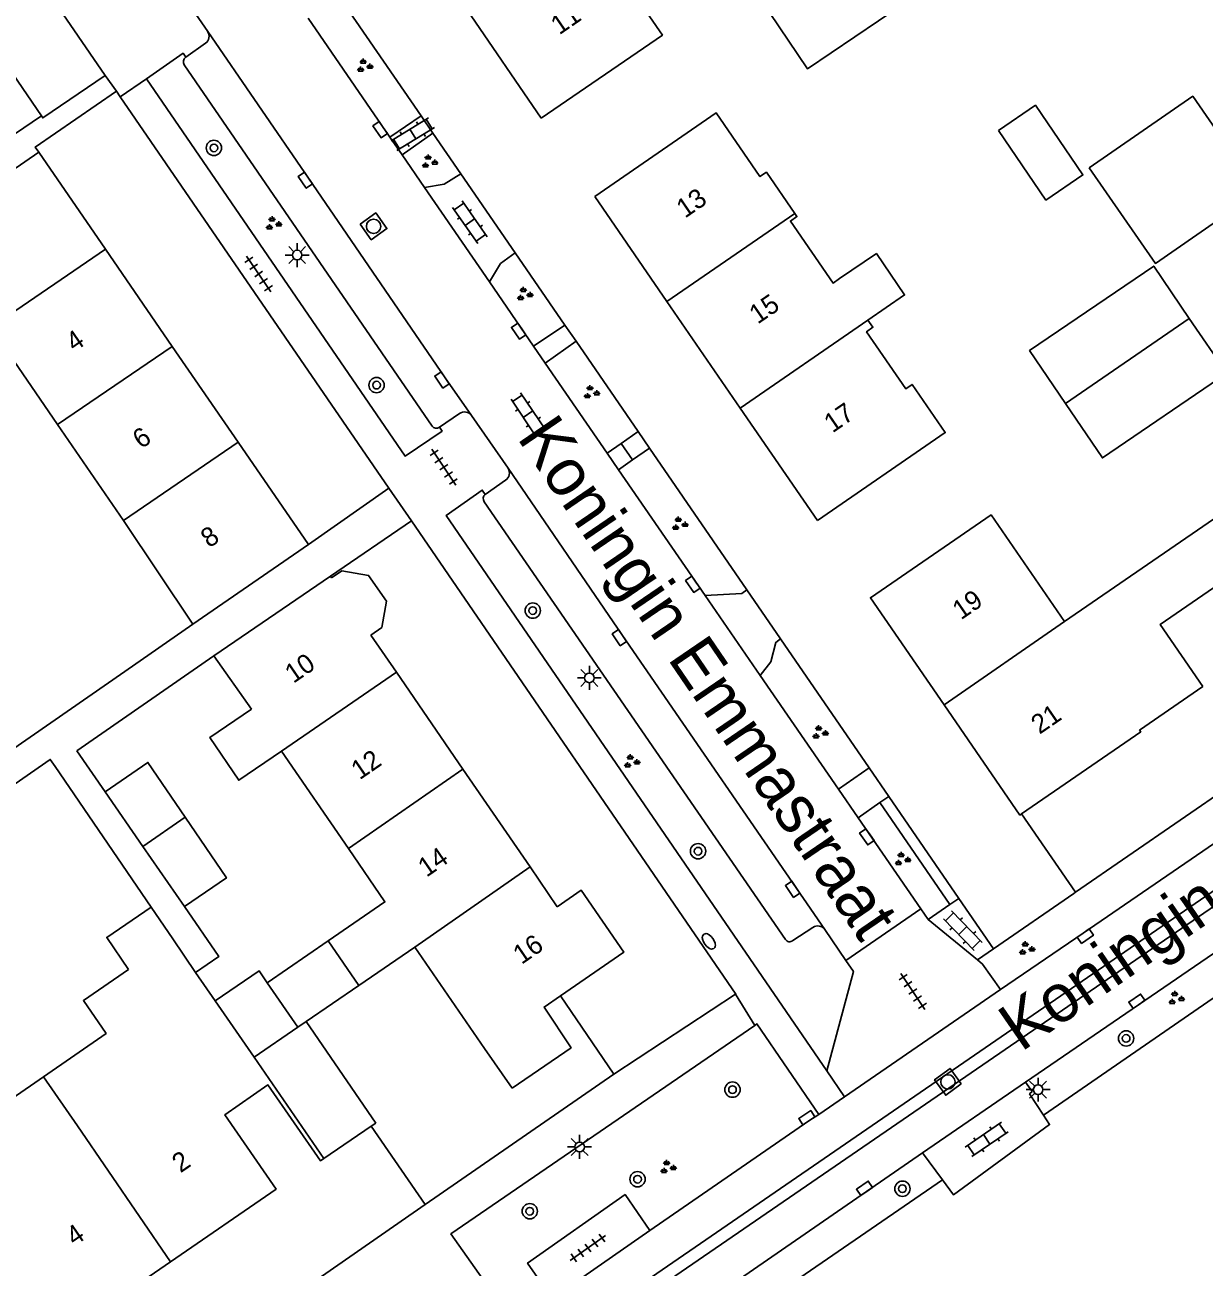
# Model space of a CAD drawing. Extents: x 137999 to 141000, y 397500 to 400501.
# Drawn here: x 138164.6 to 138226.2, y 399868.5 to 399933.3 of the extents above; entities that cross this region are included whole.
import ezdxf

# ---------------------------------------------------------------- set-up
doc = ezdxf.new("R2010")
doc.units = 0
for name, color, linetype in [('gg-afsc-erfafscheiding', 7, 'Continuous'), ('gg-afsc-hekwerk', 7, 'Continuous'), ('gg-afsc-muur', 7, 'Continuous'), ('gg-anno-huisnummerreeks BGT', 7, 'Continuous'), ('gg-anno-openbare ruimte label', 7, 'Continuous'), ('gg-bbg-bijgebouw', 7, 'Continuous'), ('gg-bbg-gedigitaliseerde bebouwing', 7, 'Continuous'), ('gg-bbg-gedigitaliseerde bijgebouw', 7, 'Continuous'), ('gg-bbg-hoofdgebouw', 7, 'Continuous'), ('gg-bbg-luifel en loopbrug', 7, 'Continuous'), ('gg-bbg-tussenscheiding', 7, 'Continuous'), ('gg-knt-verharding', 7, 'Continuous'), ('gg-knt-verharding nz', 7, 'Continuous'), ('gt-grn-groengrens', 7, 'Continuous'), ('gt-grn-vlakafsluiter', 7, 'Continuous'), ('gt-grn-weggrens', 7, 'Continuous'), ('gt-symb-boom', 7, 'Continuous'), ('gt-symb-brandkraan', 7, 'Continuous'), ('gt-symb-groenvak', 7, 'Continuous'), ('gt-symb-klinker verharding', 7, 'Continuous'), ('gt-symb-kolk', 7, 'Continuous'), ('gt-symb-lichtmast', 7, 'Continuous'), ('gt-symb-rioolschacht', 7, 'Continuous'), ('gt-symb-tegel verharding', 7, 'Continuous')]:
    doc.layers.add(name, color=color, linetype=linetype)

# ---------------------------------------------------------------- blocks, each defined once
blk = doc.blocks.new('gt0-GRVAK')
at = {"layer": 'gt-symb-groenvak'}
for p, q in [((-0.11, 0.189), (-0.228, 0.24)), ((-0.182, 0.153), (0.088, 0.153)), ((-0.091, 0.211), (-0.156, 0.322)), ((-0.047, 0.214), (-0.047, 0.393)), ((-0.004, 0.211), (0.061, 0.322)), ((0.015, 0.189), (0.133, 0.24)), ((0.262, -0.052), (0.197, 0.059)), ((0.305, -0.049), (0.305, 0.13)), ((0.349, -0.052), (0.414, 0.059)), ((-0.245, -0.228), (-0.363, -0.177)), ((-0.318, -0.264), (-0.047, -0.264)), ((-0.226, -0.206), (-0.291, -0.095)), ((-0.183, -0.203), (-0.183, -0.024)), ((-0.139, -0.206), (-0.074, -0.095)), ((-0.12, -0.228), (-0.002, -0.177)), ((0.243, -0.074), (0.125, -0.023)), ((0.17, -0.11), (0.441, -0.11)), ((0.368, -0.074), (0.486, -0.023))]:
    blk.add_line(p, q, dxfattribs=at)
blk = doc.blocks.new('gt0-KL1')
at = {"layer": 'gt-symb-klinker verharding'}
for p, q in [((-1.15, 0.3), (1.15, 0.3)), ((-1, -0.3), (-1, 0.3)), ((-0.5, 0.3), (-0.5, 0.45)), ((0, -0.3), (0, 0.3)), ((0.5, 0.3), (0.5, 0.45)), ((1, -0.3), (1, 0.3)), ((-1.15, -0.3), (1.15, -0.3)), ((-0.5, -0.45), (-0.5, -0.3)), ((0.5, -0.45), (0.5, -0.3))]:
    blk.add_line(p, q, dxfattribs=at)
blk = doc.blocks.new('gt0-KOLK')
at = {"layer": 'gt-symb-kolk'}
blk.add_lwpolyline([(0, 0), (0.375, 0), (0.375, 0.4), (-0.375, 0.4), (-0.375, 0), (0, 0)], dxfattribs=at)
blk = doc.blocks.new('gt0-BOOM')
at = {"layer": 'gt-symb-boom'}
for radius in [0.4, 0.2]:
    blk.add_circle((0, 0), radius, dxfattribs=at)
blk = doc.blocks.new('gt0-LMAST')
at = {"layer": 'gt-symb-lichtmast'}
for p, q in [((-0.182, 0.173), (-0.447, 0.438)), ((-0.005, 0.246), (-0.005, 0.621)), ((0.172, 0.173), (0.437, 0.438)), ((-0.255, -0.004), (-0.63, -0.004)), ((-0.182, -0.181), (-0.447, -0.446)), ((-0.005, -0.254), (-0.005, -0.629)), ((0.437, -0.446), (0.172, -0.181)), ((0.245, -0.004), (0.62, -0.004))]:
    blk.add_line(p, q, dxfattribs=at)
blk.add_circle((-0.005, -0.004), 0.25, dxfattribs=at)
blk = doc.blocks.new('gt0-TEG1')
at = {"layer": 'gt-symb-tegel verharding'}
for p, q in [((-1.125, 0), (1.125, 0)), ((-0.9, -0.25), (-0.9, 0.25)), ((-0.45, -0.25), (-0.45, 0.25)), ((0, -0.25), (0, 0.25)), ((0.45, -0.25), (0.45, 0.25)), ((0.9, -0.25), (0.9, 0.25))]:
    blk.add_line(p, q, dxfattribs=at)
blk = doc.blocks.new('gt0-RS')
at = {"layer": 'gt-symb-rioolschacht'}
blk.add_lwpolyline([(-0.5, -0.5), (0.5, -0.5), (0.5, 0.5), (-0.5, 0.5)], close=True, dxfattribs=at)
blk.add_circle((0, 0), 0.375, dxfattribs=at)
blk = doc.blocks.new('gt0-BR')
at = {"layer": 'gt-symb-brandkraan'}
for centre, radius, start, end in [((-0.244, 0), 0.206, 107.56694, 252.43307), ((0.599, -2.664), 3, 106.89205, 107.56694), ((0, -0.691), 0.938, 73.10799, 106.89205), ((-0.599, -2.664), 3, 72.43309, 73.10799), ((0.244, 0), 0.206, 287.56695, 72.43309), ((0.599, 2.664), 3, 252.43307, 253.10797), ((0, 0.691), 0.938, 253.10797, 286.89206), ((-0.599, 2.664), 3, 286.89206, 287.56695)]:
    blk.add_arc(centre, radius, start, end, dxfattribs=at)

msp = doc.modelspace()

# ---------------------------------------------------------------- linework, layer by layer
at = {"layer": 'gg-afsc-erfafscheiding'}
for p, q in [((138173.372, 399902.013), (138169.814, 399899.547)), ((138167.311, 399895.395), (138168.781, 399893.269)), ((138166.183, 399894.589), (138171.193, 399887.241)), ((138216.635, 399892.109), (138219.456, 399888.019))]:
    msp.add_line(p, q, dxfattribs=at)
for points in [[(138157.271, 399893.932), (138154.118, 399888.663), (138169.814, 399899.547)], [(138172.928, 399887.272), (138174.727, 399884.669), (138173.512, 399883.829)], [(138186.75, 399836.588), (138178.901, 399848.232), (138179.379, 399850.047), (138205.064, 399867.897), (138212.505, 399873.019)]]:
    msp.add_lwpolyline(points, dxfattribs=at)
at = {"layer": 'gg-afsc-hekwerk'}
for p, q in [((138219.456, 399888.019), (138234.264, 399898.232)), ((138219.362, 399887.954), (138219.456, 399888.019))]:
    msp.add_line(p, q, dxfattribs=at)
at = {"layer": 'gg-afsc-muur'}
for p, q in [((138167.311, 399895.395), (138174.472, 399900.357)), ((138195.357, 399878.535), (138192.572, 399882.619)), ((138185.501, 399871.719), (138195.357, 399878.535)), ((138182.684, 399875.809), (138185.501, 399871.719))]:
    msp.add_line(p, q, dxfattribs=at)
msp.add_lwpolyline([(138162.241, 399892.403), (138165.926, 399894.959), (138166.183, 399894.589)], dxfattribs=at)
at = {"layer": 'gg-bbg-bijgebouw'}
for p, q in [((138163.21, 399931.84), (138165.46, 399928.54)), ((138182.684, 399875.809), (138180.215, 399874.12)), ((138182.92, 399875.97), (138182.684, 399875.809))]:
    msp.add_line(p, q, dxfattribs=at)
at = {"layer": 'gg-bbg-gedigitaliseerde bebouwing'}
for p, q in [((138165.32, 399926.65), (138159.36, 399922.531)), ((138162.821, 399917.5), (138166.305, 399912.434)), ((138166.305, 399912.434), (138169.752, 399907.422)), ((138218.889, 399902.156), (138227.552, 399908.096)), ((138169.752, 399907.422), (138173.372, 399902.013)), ((138174.472, 399900.357), (138176.437, 399897.586)), ((138177.999, 399895.384), (138181.489, 399890.303)), ((138172.316, 399885.595), (138171.193, 399887.241)), ((138172.316, 399885.595), (138173.512, 399883.829)), ((138180.435, 399885.486), (138182.039, 399883.15)), ((138182.039, 399883.15), (138184.952, 399885.15)), ((138184.952, 399885.15), (138188.6, 399879.87)), ((138173.512, 399883.829), (138174.537, 399882.356)), ((138190.04, 399877.796), (138188.6, 399879.87))]:
    msp.add_line(p, q, dxfattribs=at)
for points in [[(138191.56, 399928.42), (138197.884, 399932.764), (138195.601, 399936.09), (138195.924, 399936.312)], [(138204.793, 399923.454), (138203.315, 399925.603), (138202.98, 399925.373), (138200.695, 399928.698), (138194.35, 399924.34)], [(138207.132, 399920.048), (138206.799, 399919.819), (138204.573, 399923.056), (138204.908, 399923.286), (138204.793, 399923.454)], [(138208.621, 399917.883), (138210.531, 399919.198), (138209.057, 399921.36), (138207.132, 399920.048)], [(138205.98, 399907.42), (138212.651, 399912.018), (138210.924, 399914.53), (138210.592, 399914.301), (138208.544, 399917.281), (138208.877, 399917.51), (138208.621, 399917.883)], [(138226.099, 399898.757), (138223.87, 399901.997), (138229.22, 399905.676)], [(138176.437, 399897.586), (138174.248, 399896.097), (138175.767, 399893.865), (138177.999, 399895.384)], [(138181.489, 399890.303), (138183.399, 399887.522), (138180.435, 399885.486)], [(138171.193, 399887.241), (138168.874, 399885.663), (138170.007, 399883.998)], [(138170.007, 399883.998), (138167.652, 399882.37), (138168.837, 399880.657), (138165.567, 399878.396)], [(138157.77, 399873.004), (138154.542, 399877.672), (138157.327, 399879.598), (138159.798, 399877.298), (138161.14, 399878.241), (138162.5, 399876.275), (138165.567, 399878.396)]]:
    msp.add_lwpolyline(points, dxfattribs=at)
at = {"layer": 'gg-bbg-gedigitaliseerde bijgebouw'}
for p, q in [((138159.316, 399924.381), (138165.46, 399928.54)), ((138170.759, 399890.409), (138168.781, 399893.269)), ((138172.928, 399887.272), (138170.759, 399890.409)), ((138178.846, 399880.973), (138177.252, 399883.299)), ((138179.285, 399881.274), (138178.846, 399880.973)), ((138182.92, 399875.97), (138179.285, 399881.274))]:
    msp.add_line(p, q, dxfattribs=at)
for points in [[(138211.634, 399935.184), (138205.466, 399930.997), (138203.471, 399933.935)], [(138220.174, 399925.837), (138223.626, 399920.844), (138229.027, 399924.578), (138225.574, 399929.571), (138220.174, 399925.837)], [(138215.439, 399927.783), (138217.364, 399929.096), (138219.84, 399925.464), (138217.915, 399924.152), (138215.439, 399927.783)], [(138225.387, 399917.966), (138223.538, 399920.702), (138217.056, 399916.29), (138218.934, 399913.53)], [(138218.934, 399913.53), (138220.863, 399910.696), (138227.35, 399915.112), (138225.387, 399917.966)], [(138172.97, 399891.934), (138171.023, 399894.795), (138168.781, 399893.269)], [(138172.97, 399891.934), (138175.125, 399888.767), (138172.928, 399887.272)], [(138177.252, 399883.299), (138176.824, 399883.923), (138174.537, 399882.356)]]:
    msp.add_lwpolyline(points, dxfattribs=at)
at = {"layer": 'gg-bbg-hoofdgebouw'}
for p, q in [((138191.56, 399928.42), (138187.668, 399934.091)), ((138165.32, 399926.65), (138168.802, 399921.588)), ((138198.124, 399918.85), (138194.35, 399924.34)), ((138168.802, 399921.588), (138172.291, 399916.515)), ((138201.947, 399913.288), (138198.124, 399918.85)), ((138172.291, 399916.515), (138175.733, 399911.511)), ((138205.98, 399907.42), (138201.947, 399913.288)), ((138175.733, 399911.511), (138179.4, 399906.18)), ((138179.4, 399906.18), (138173.372, 399902.013)), ((138174.472, 399900.357), (138180.55, 399904.52)), ((138180.55, 399904.52), (138180.611, 399904.431)), ((138182.659, 399901.449), (138183.994, 399899.506)), ((138183.994, 399899.506), (138187.468, 399894.448)), ((138226.099, 399898.757), (138222.803, 399896.482)), ((138187.468, 399894.448), (138190.975, 399889.341)), ((138190.975, 399889.341), (138192.398, 399887.269))]:
    msp.add_line(p, q, dxfattribs=at)
for points in [[(138218.889, 399902.156), (138215.05, 399907.72), (138208.75, 399903.39), (138212.59, 399897.808)], [(138180.611, 399904.431), (138181.139, 399904.793), (138182.545, 399904.56), (138183.487, 399903.218), (138183.232, 399901.843), (138182.659, 399901.449)], [(138216.635, 399892.109), (138216.55, 399892.05), (138212.59, 399897.808)], [(138222.803, 399896.482), (138222.86, 399896.4), (138216.635, 399892.109)], [(138192.572, 399882.619), (138195.871, 399884.888), (138193.648, 399888.127), (138192.398, 399887.269)], [(138192.572, 399882.619), (138191.712, 399882.027), (138193.121, 399879.905), (138190.04, 399877.796)], [(138180.215, 399874.12), (138180.04, 399874), (138177.29, 399877.97), (138175.04, 399876.41), (138177.71, 399872.53), (138172.2, 399868.735)], [(138172.2, 399868.735), (138166.69, 399864.94), (138164.956, 399867.476)]]:
    msp.add_lwpolyline(points, dxfattribs=at)
at = {"layer": 'gg-bbg-luifel en loopbrug'}
for p, q in [((138180.435, 399885.486), (138177.252, 399883.299)), ((138182.039, 399883.15), (138179.285, 399881.274))]:
    msp.add_line(p, q, dxfattribs=at)
at = {"layer": 'gg-bbg-tussenscheiding'}
for p, q in [((138198.124, 399918.85), (138204.793, 399923.454)), ((138162.821, 399917.5), (138168.802, 399921.588)), ((138208.621, 399917.883), (138201.947, 399913.288)), ((138225.387, 399917.966), (138218.934, 399913.53)), ((138172.291, 399916.515), (138166.305, 399912.434)), ((138169.752, 399907.422), (138175.733, 399911.511)), ((138218.889, 399902.156), (138212.59, 399897.808)), ((138177.999, 399895.384), (138183.994, 399899.506)), ((138187.468, 399894.448), (138181.489, 399890.303)), ((138170.759, 399890.409), (138172.97, 399891.934)), ((138184.952, 399885.15), (138190.975, 399889.341)), ((138176.567, 399879.411), (138174.537, 399882.356)), ((138176.567, 399879.411), (138178.846, 399880.973)), ((138176.567, 399879.411), (138180.215, 399874.12)), ((138167.34, 399875.831), (138165.567, 399878.396)), ((138172.2, 399868.735), (138167.34, 399875.831))]:
    msp.add_line(p, q, dxfattribs=at)
at = {"layer": 'gg-knt-verharding'}
for p, q in [((138171.372, 399936.98), (138174.142, 399932.942)), ((138168.789, 399930.657), (138166.578, 399933.87)), ((138183.66, 399927.431), (138179.387, 399933.649)), ((138174.037, 399932.331), (138172.995, 399931.61)), ((138172.916, 399931.21), (138185.857, 399912.345)), ((138169.577, 399929.53), (138169.373, 399929.826)), ((138183.607, 399909.106), (138169.577, 399929.53)), ((138185.284, 399928.551), (138183.66, 399927.431)), ((138184.298, 399926.503), (138185.905, 399927.647)), ((138185.46, 399924.814), (138184.298, 399926.503)), ((138191.159, 399916.529), (138188.851, 399919.884)), ((138192.798, 399917.619), (138191.159, 399916.529)), ((138191.769, 399915.643), (138193.375, 399916.779)), ((138195.009, 399910.933), (138191.769, 399915.643)), ((138186.243, 399912.294), (138187.288, 399913.01)), ((138187.921, 399912.904), (138189.832, 399910.152)), ((138196.617, 399912.062), (138195.725, 399911.449)), ((138195.725, 399911.449), (138195.009, 399910.933)), ((138196.322, 399910.595), (138195.725, 399911.449)), ((138197.207, 399911.204), (138196.322, 399910.595)), ((138195.599, 399910.075), (138196.322, 399910.595)), ((138200.12, 399903.506), (138195.599, 399910.075)), ((138189.698, 399909.524), (138188.64, 399908.79)), ((138179.4, 399906.18), (138183.607, 399909.106)), ((138188.577, 399908.407), (138204.306, 399885.557)), ((138180.55, 399904.52), (138184.786, 399907.406)), ((138242.972, 399899.292), (138119.076, 399814.219)), ((138207.087, 399893.404), (138202.993, 399899.34)), ((138119.47, 399813.69), (138243.348, 399898.735)), ((138235.785, 399896.792), (138219.859, 399885.893)), ((138208.677, 399894.517), (138207.087, 399893.404)), ((138209.241, 399892.703), (138209.702, 399893.026)), ((138208.114, 399891.914), (138209.241, 399892.703)), ((138209.241, 399892.703), (138212.894, 399887.381)), ((138211.385, 399887.149), (138208.114, 399891.914)), ((138219.362, 399887.954), (138215.177, 399885.068)), ((138207.469, 399884.461), (138211.385, 399887.149)), ((138211.385, 399887.149), (138211.762, 399886.607)), ((138211.762, 399886.607), (138212.894, 399887.381)), ((138213.361, 399887.702), (138212.894, 399887.381)), ((138211.762, 399886.607), (138214.338, 399884.489)), ((138204.697, 399885.498), (138205.738, 399886.191)), ((138206.373, 399886.076), (138207.469, 399884.461)), ((138215.546, 399882.938), (138219.859, 399885.893)), ((138216.851, 399878.105), (138228.396, 399886.01)), ((138215.177, 399885.068), (138214.338, 399884.489)), ((138217.781, 399876.393), (138230.183, 399884.94)), ((138201.71, 399882.7), (138195.357, 399878.535)), ((138207.399, 399877.351), (138215.546, 399882.938)), ((138216.851, 399878.105), (138211.472, 399874.42)), ((138206.057, 399876.431), (138207.399, 399877.351)), ((138206.057, 399876.431), (138205.539, 399876.09)), ((138205.539, 399876.09), (138197.226, 399870.367)), ((138177.737, 399851.178), (138211.472, 399874.42)), ((138211.472, 399874.42), (138212.505, 399873.019)), ((138185.501, 399871.719), (138136.135, 399837.595)), ((138197.226, 399870.367), (138192.127, 399866.821))]:
    msp.add_line(p, q, dxfattribs=at)
for points in [[(138170.956, 399930.47), (138172.854, 399931.81), (138172.995, 399931.61)], [(138165.46, 399928.54), (138165.531, 399928.436), (138168.789, 399930.657)], [(138186.243, 399912.294), (138186.379, 399912.094), (138184.453, 399910.785), (138170.956, 399930.47)], [(138169.373, 399929.826), (138165.139, 399926.913), (138165.32, 399926.65)], [(138187.367, 399925.52), (138186.484, 399924.981), (138185.46, 399924.814)], [(138188.851, 399919.884), (138189.438, 399920.838), (138190.206, 399921.39)], [(138206.47, 399878.706), (138186.591, 399907.683), (138188.482, 399909.015), (138188.64, 399908.79)], [(138184.786, 399907.406), (138201.726, 399882.71), (138201.71, 399882.7)], [(138200.12, 399903.506), (138202.03, 399903.617), (138202.286, 399903.814)], [(138202.993, 399899.34), (138203.556, 399900.051), (138203.806, 399901.061), (138204.048, 399901.251)], [(138207.469, 399884.461), (138207.86, 399883.886), (138206.47, 399878.706)], [(138214.338, 399884.489), (138214.605, 399884.27), (138215.546, 399882.938)], [(138202.706, 399881.074), (138186.842, 399870.193), (138190.174, 399865.469)], [(138206.057, 399876.431), (138202.82, 399881.152), (138202.706, 399881.074)], [(138217.781, 399876.393), (138217.061, 399877.494), (138217.191, 399877.626), (138216.851, 399878.105)], [(138212.505, 399873.019), (138213.092, 399872.224), (138218.103, 399875.899), (138217.781, 399876.393)], [(138197.226, 399870.367), (138195.939, 399872.243), (138190.847, 399868.668), (138192.127, 399866.821)]]:
    msp.add_lwpolyline(points, dxfattribs=at)
for centre, radius, start, end in [((138173.759, 399932.693), 0.456, 307.46924, 33.02875), ((138173.162, 399931.369), 0.293, 124.76796, 212.88777), ((138187.55, 399912.631), 0.46, 36.29755, 124.68975), ((138186.078, 399912.529), 0.287, 219.80778, 305.13907), ((138189.426, 399909.91), 0.473, 305.1884, 30.7218), ((138188.817, 399908.564), 0.287, 128.12309, 213.19494), ((138205.991, 399885.775), 0.486, 38.18642, 121.2833), ((138204.528, 399885.705), 0.267, 213.72428, 309.11389)]:
    msp.add_arc(centre, radius, start, end, dxfattribs=at)
at = {"layer": 'gg-knt-verharding nz'}
for p, q in [((138183.66, 399927.431), (138184.298, 399926.503)), ((138185.46, 399924.814), (138188.851, 399919.884)), ((138191.159, 399916.529), (138191.769, 399915.643)), ((138195.009, 399910.933), (138195.599, 399910.075)), ((138200.12, 399903.506), (138202.993, 399899.34)), ((138207.087, 399893.404), (138208.114, 399891.914))]:
    msp.add_line(p, q, dxfattribs=at)
for points in [[(138174.142, 399932.942), (138179.41, 399925.299), (138186.544, 399914.876), (138187.921, 399912.904)], [(138189.832, 399910.152), (138195.805, 399901.421), (138206.373, 399886.076)]]:
    msp.add_lwpolyline(points, dxfattribs=at)
at = {"layer": 'gt-grn-groengrens'}
for p, q in [((138180.993, 399934.794), (138185.284, 399928.551)), ((138185.905, 399927.647), (138187.367, 399925.52)), ((138192.798, 399917.619), (138190.206, 399921.39)), ((138196.617, 399912.062), (138193.375, 399916.779)), ((138202.286, 399903.814), (138197.207, 399911.204)), ((138208.677, 399894.517), (138204.048, 399901.251)), ((138213.361, 399887.702), (138209.702, 399893.026))]:
    msp.add_line(p, q, dxfattribs=at)
at = {"layer": 'gt-grn-vlakafsluiter'}
for p, q in [((138185.284, 399928.551), (138185.905, 399927.647)), ((138187.367, 399925.52), (138190.206, 399921.39)), ((138192.798, 399917.619), (138193.375, 399916.779)), ((138196.617, 399912.062), (138197.207, 399911.204)), ((138202.286, 399903.814), (138204.048, 399901.251)), ((138208.677, 399894.517), (138209.702, 399893.026)), ((138213.361, 399887.702), (138215.177, 399885.068))]:
    msp.add_line(p, q, dxfattribs=at)
at = {"layer": 'gt-grn-weggrens'}
for p, q in [((138169.373, 399929.826), (138168.789, 399930.657)), ((138170.956, 399930.47), (138169.577, 399929.53)), ((138184.786, 399907.406), (138183.607, 399909.106)), ((138202.706, 399881.074), (138201.71, 399882.7)), ((138206.47, 399878.706), (138207.399, 399877.351))]:
    msp.add_line(p, q, dxfattribs=at)

# ---------------------------------------------------------------- block references
at = {"layer": 'gt-symb-boom'}
for p in [(138174.467, 399926.871), (138182.96, 399914.49), (138191.117, 399902.722), (138199.747, 399890.166), (138222.1, 399880.393), (138201.546, 399877.719), (138196.587, 399873.043), (138210.421, 399872.55), (138190.962, 399871.373)]:
    msp.add_blockref('gt0-BOOM', p, dxfattribs=at)
at = {"layer": 'gt-symb-brandkraan', "rotation": -55.12366859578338}
msp.add_blockref('gt0-BR', (138200.311, 399885.462), dxfattribs=at)
at = {"layer": 'gt-symb-groenvak'}
for p in [(138182.31, 399931.144), (138185.699, 399926.141), (138177.55, 399922.915), (138190.668, 399919.226), (138194.152, 399914.102), (138198.764, 399907.235), (138206.092, 399896.346), (138196.254, 399894.834), (138210.396, 399889.736), (138216.878, 399885.073), (138224.685, 399882.487), (138198.154, 399873.659)]:
    msp.add_blockref('gt0-GRVAK', p, dxfattribs=at)
at = {"layer": 'gt-symb-klinker verharding'}
for p, rotation in [((138184.852, 399927.594), 31.464873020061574), ((138187.837, 399922.995), -55.05490123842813), ((138190.873, 399912.974), -56.08748741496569), ((138213.573, 399886.021), -45.972395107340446), ((138214.821, 399875.123), -145.59476571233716)]:
    msp.add_blockref('gt0-KL1', p, dxfattribs=dict(at, rotation=rotation))
at = {"layer": 'gt-symb-kolk'}
for p, rotation in [((138183.314, 399927.935), 124.52265326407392), ((138179.41, 399925.299), 124.57419147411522), ((138190.545, 399917.422), 124.52722699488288), ((138186.544, 399914.876), 124.38840709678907), ((138199.639, 399904.204), 124.59205961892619), ((138195.805, 399901.421), 124.37718999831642), ((138208.727, 399891.025), 124.43537647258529), ((138204.85, 399888.285), 124.5517446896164), ((138219.859, 399885.893), -145.59476571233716), ((138222.772, 399882.169), 34.48490803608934), ((138205.539, 399876.09), 33.038284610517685), ((138208.553, 399872.405), 34.48490803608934)]:
    msp.add_blockref('gt0-KOLK', p, dxfattribs=dict(at, rotation=rotation))
at = {"layer": 'gt-symb-lichtmast'}
for p in [(138178.82, 399921.283), (138194.076, 399899.215), (138217.509, 399877.723), (138193.567, 399874.732)]:
    msp.add_blockref('gt0-LMAST', p, dxfattribs=at)
at = {"layer": 'gt-symb-rioolschacht'}
for p, rotation in [((138182.803, 399922.779), -54.61991850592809), ((138212.794, 399878.126), 126.01052540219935)]:
    msp.add_blockref('gt0-RS', p, dxfattribs=dict(at, rotation=rotation))
at = {"layer": 'gt-symb-tegel verharding'}
for p, rotation in [((138176.802, 399920.29), 124.69152882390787), ((138186.466, 399910.207), -56.087487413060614), ((138210.96, 399882.844), -56.08748741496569), ((138193.998, 399869.455), 35.10468688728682)]:
    msp.add_blockref('gt0-TEG1', p, dxfattribs=dict(at, rotation=rotation))

# ---------------------------------------------------------------- texts
at = {"layer": 'gg-anno-huisnummerreeks BGT'}
for s, p in [('11', (138192.502, 399932.744)), ('13', (138199.063, 399923.174)), ('15', (138202.862, 399917.647)), ('4', (138167.18, 399916.202)), ('17', (138206.767, 399911.966)), ('6', (138170.667, 399911.133)), ('8', (138174.221, 399905.965)), ('19', (138213.474, 399902.209)), ('10', (138178.618, 399898.896)), ('21', (138217.58, 399896.24)), ('12', (138182.077, 399893.861)), ('14', (138185.567, 399888.778)), ('16', (138190.531, 399884.227)), ('2', (138172.725, 399873.347)), ('4', (138167.188, 399869.533))]:
    msp.add_text(s, height=1, rotation=34.5, dxfattribs=at).set_placement(p)
at = {"layer": 'gg-anno-openbare ruimte label'}
for s, rotation, p in [('Koningin Emmastraat', 304.3, (138190.259, 399911.749)), ('Koningin Julianastraat', 34.6, (138216.614, 399879.657))]:
    msp.add_text(s, height=2.5, rotation=rotation, dxfattribs=at).set_placement(p)

doc.saveas('drawing.dxf')
